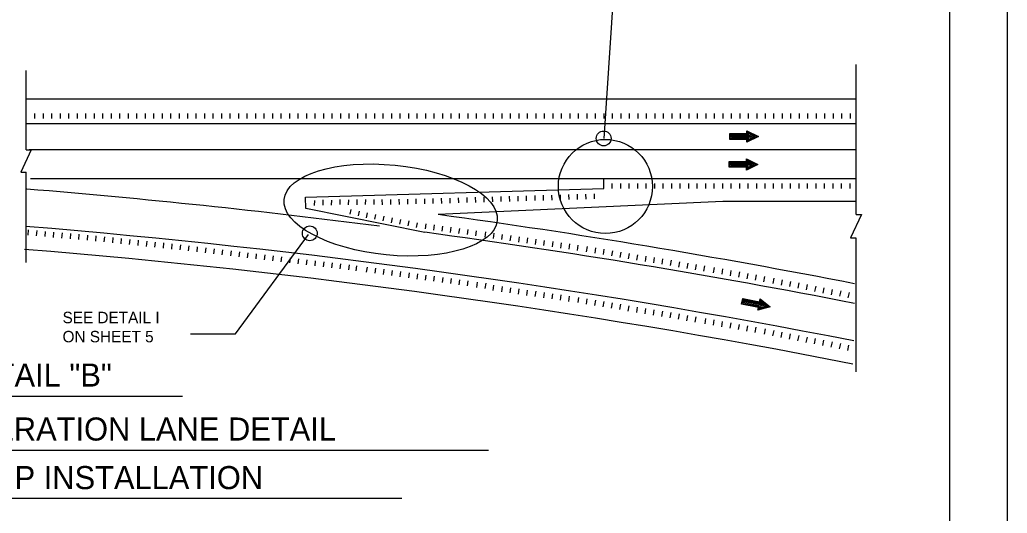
# Model space of a CAD drawing. Extents: x 632008 to 634206, y 294231 to 297795.
# Drawn here: x 632590.2 to 632848.9, y 295746 to 295875.2 of the extents above; entities that cross this region are included whole.
import ezdxf

# ---------------------------------------------------------------- set-up
doc = ezdxf.new("R2010")
doc.units = 0
for name, color, linetype in [('1', 7, 'Continuous'), ('2', 7, 'Continuous'), ('PLT-BNDY', 7, 'Continuous')]:
    doc.layers.add(name, color=color, linetype=linetype)

msp = doc.modelspace()

# ---------------------------------------------------------------- linework, layer by layer
at = {"layer": '1'}
for p, q in [((632747.02, 295902.24), (632743.17, 295844.09)), ((632594.1, 295850.65), (632594.1, 295849.32)), ((632596.33, 295850.65), (632596.33, 295849.32)), ((632598.56, 295850.65), (632598.56, 295849.32)), ((632600.78, 295850.65), (632600.78, 295849.32)), ((632603.01, 295850.65), (632603.01, 295849.32)), ((632605.23, 295850.65), (632605.23, 295849.32)), ((632607.45, 295850.65), (632607.45, 295849.32)), ((632609.68, 295850.65), (632609.68, 295849.32)), ((632611.91, 295850.65), (632611.91, 295849.32)), ((632614.13, 295850.65), (632614.13, 295849.32)), ((632616.35, 295850.65), (632616.35, 295849.32)), ((632618.58, 295850.65), (632618.58, 295849.32)), ((632620.81, 295850.65), (632620.81, 295849.32)), ((632623.03, 295850.65), (632623.03, 295849.32)), ((632625.25, 295850.65), (632625.25, 295849.32)), ((632627.48, 295850.65), (632627.48, 295849.32)), ((632629.7, 295850.65), (632629.7, 295849.32)), ((632631.93, 295850.65), (632631.93, 295849.32)), ((632634.16, 295850.65), (632634.16, 295849.32)), ((632636.38, 295850.65), (632636.38, 295849.32)), ((632638.6, 295850.65), (632638.6, 295849.32)), ((632640.83, 295850.65), (632640.83, 295849.32)), ((632643.05, 295850.65), (632643.05, 295849.32)), ((632645.28, 295850.65), (632645.28, 295849.32)), ((632647.5, 295850.65), (632647.5, 295849.32)), ((632649.73, 295850.65), (632649.73, 295849.32)), ((632651.95, 295850.65), (632651.95, 295849.32)), ((632654.18, 295850.65), (632654.18, 295849.32)), ((632656.4, 295850.65), (632656.4, 295849.32)), ((632658.63, 295850.65), (632658.63, 295849.32)), ((632660.85, 295850.65), (632660.85, 295849.32)), ((632663.08, 295850.65), (632663.08, 295849.32)), ((632665.3, 295850.65), (632665.3, 295849.32)), ((632667.53, 295850.65), (632667.53, 295849.32)), ((632669.75, 295850.65), (632669.75, 295849.32)), ((632671.98, 295850.65), (632671.98, 295849.32)), ((632674.2, 295850.65), (632674.2, 295849.32)), ((632676.43, 295850.65), (632676.43, 295849.32)), ((632678.65, 295850.65), (632678.65, 295849.32)), ((632680.88, 295850.65), (632680.88, 295849.32)), ((632683.1, 295850.65), (632683.1, 295849.32)), ((632685.33, 295850.65), (632685.33, 295849.32)), ((632687.55, 295850.65), (632687.55, 295849.32)), ((632689.78, 295850.65), (632689.78, 295849.32)), ((632692, 295850.65), (632692, 295849.32)), ((632694.23, 295850.65), (632694.23, 295849.32)), ((632696.45, 295850.65), (632696.45, 295849.32)), ((632698.68, 295850.65), (632698.68, 295849.32)), ((632700.9, 295850.65), (632700.9, 295849.32)), ((632703.13, 295850.65), (632703.13, 295849.32)), ((632705.35, 295850.65), (632705.35, 295849.32)), ((632707.58, 295850.65), (632707.58, 295849.32)), ((632709.8, 295850.65), (632709.8, 295849.32)), ((632712.03, 295850.65), (632712.03, 295849.32)), ((632714.25, 295850.65), (632714.25, 295849.32)), ((632716.48, 295850.65), (632716.48, 295849.32)), ((632718.7, 295850.65), (632718.7, 295849.32)), ((632720.93, 295850.65), (632720.93, 295849.32)), ((632723.15, 295850.65), (632723.15, 295849.32)), ((632725.38, 295850.65), (632725.38, 295849.32)), ((632727.6, 295850.65), (632727.6, 295849.32)), ((632729.83, 295850.65), (632729.83, 295849.32)), ((632732.05, 295850.65), (632732.05, 295849.32)), ((632734.28, 295850.65), (632734.28, 295849.32)), ((632736.5, 295850.65), (632736.5, 295849.32)), ((632738.73, 295850.65), (632738.73, 295849.32)), ((632740.95, 295850.65), (632740.95, 295849.32)), ((632743.18, 295850.65), (632743.18, 295849.32)), ((632745.4, 295850.65), (632745.4, 295849.32)), ((632747.63, 295850.65), (632747.63, 295849.32)), ((632749.85, 295850.65), (632749.85, 295849.32)), ((632752.08, 295850.65), (632752.08, 295849.32)), ((632754.3, 295850.65), (632754.3, 295849.32)), ((632756.53, 295850.65), (632756.53, 295849.32)), ((632758.75, 295850.65), (632758.75, 295849.32)), ((632760.98, 295850.65), (632760.98, 295849.32)), ((632763.2, 295850.65), (632763.2, 295849.32)), ((632765.43, 295850.65), (632765.43, 295849.32)), ((632767.65, 295850.65), (632767.65, 295849.32)), ((632769.88, 295850.65), (632769.88, 295849.32)), ((632772.1, 295850.65), (632772.1, 295849.32)), ((632774.33, 295850.65), (632774.33, 295849.32)), ((632776.55, 295850.65), (632776.55, 295849.32)), ((632778.78, 295850.65), (632778.78, 295849.32)), ((632781, 295850.65), (632781, 295849.32)), ((632783.23, 295850.65), (632783.23, 295849.32)), ((632785.45, 295850.65), (632785.45, 295849.32)), ((632787.68, 295850.65), (632787.68, 295849.32)), ((632789.9, 295850.65), (632789.9, 295849.32)), ((632792.13, 295850.65), (632792.13, 295849.32)), ((632794.35, 295850.65), (632794.35, 295849.32)), ((632796.58, 295850.65), (632796.58, 295849.32)), ((632798.8, 295850.65), (632798.8, 295849.32)), ((632801.02, 295850.65), (632801.02, 295849.32)), ((632803.25, 295850.65), (632803.25, 295849.32)), ((632805.48, 295850.65), (632805.48, 295849.32)), ((632807.7, 295850.65), (632807.7, 295849.32)), ((632743.18, 295830.97), (632743.18, 295833.61)), ((632745.4, 295830.97), (632745.4, 295832.3)), ((632747.63, 295830.97), (632747.63, 295832.3)), ((632749.85, 295830.97), (632749.85, 295832.3)), ((632752.08, 295830.97), (632752.08, 295832.3)), ((632754.3, 295830.97), (632754.3, 295832.3)), ((632756.53, 295830.97), (632756.53, 295832.3)), ((632758.75, 295830.97), (632758.75, 295832.3)), ((632760.98, 295830.97), (632760.98, 295832.3)), ((632763.2, 295830.97), (632763.2, 295832.3)), ((632765.43, 295830.97), (632765.43, 295832.3)), ((632767.65, 295830.97), (632767.65, 295832.3)), ((632769.88, 295830.97), (632769.88, 295832.3)), ((632772.1, 295830.97), (632772.1, 295832.3)), ((632774.33, 295830.97), (632774.33, 295832.3)), ((632776.55, 295830.97), (632776.55, 295832.3)), ((632778.78, 295830.97), (632778.78, 295832.3)), ((632781, 295830.97), (632781, 295832.3)), ((632783.23, 295830.97), (632783.23, 295832.3)), ((632785.45, 295830.97), (632785.45, 295832.3)), ((632787.68, 295830.97), (632787.68, 295832.3)), ((632789.9, 295830.97), (632789.9, 295832.3)), ((632792.13, 295830.97), (632792.13, 295832.3)), ((632794.35, 295830.97), (632794.35, 295832.3)), ((632796.58, 295830.97), (632796.58, 295832.3)), ((632798.8, 295830.97), (632798.8, 295832.3)), ((632801.02, 295830.97), (632801.02, 295832.3)), ((632803.25, 295830.97), (632803.25, 295832.3)), ((632805.48, 295830.97), (632805.48, 295832.3)), ((632807.7, 295830.97), (632807.7, 295832.3)), ((632665.17, 295825.75), (632665.08, 295828.71)), ((632667.39, 295827.83), (632667.36, 295826.5)), ((632669.61, 295827.99), (632669.59, 295826.66)), ((632671.84, 295827.94), (632671.81, 295826.61)), ((632674.06, 295828.1), (632674.04, 295826.77)), ((632676.29, 295828.05), (632676.26, 295826.72)), ((632678.51, 295828.07), (632678.49, 295826.74)), ((632680.74, 295828.1), (632680.71, 295826.76)), ((632682.96, 295828.12), (632682.93, 295826.78)), ((632685.19, 295826.73), (632685.16, 295828.07)), ((632687.41, 295826.78), (632687.38, 295828.12)), ((632689.64, 295826.83), (632689.61, 295828.16)), ((632691.86, 295826.88), (632691.83, 295828.21)), ((632694.08, 295826.93), (632694.06, 295828.26)), ((632696.31, 295826.97), (632696.28, 295828.31)), ((632698.52, 295827.04), (632698.48, 295828.37)), ((632700.74, 295827.1), (632700.71, 295828.44)), ((632702.97, 295827.17), (632702.93, 295828.5)), ((632705.19, 295827.23), (632705.15, 295828.57)), ((632707.42, 295827.3), (632707.38, 295828.63)), ((632709.64, 295827.36), (632709.6, 295828.69)), ((632711.87, 295827.42), (632711.83, 295828.76)), ((632714.09, 295827.49), (632714.05, 295828.82)), ((632716.31, 295827.55), (632716.27, 295828.89)), ((632718.54, 295827.62), (632718.5, 295828.95)), ((632720.76, 295827.68), (632720.72, 295829.02)), ((632722.98, 295827.75), (632722.95, 295829.08)), ((632725.21, 295827.81), (632725.17, 295829.14)), ((632727.43, 295827.87), (632727.39, 295829.21)), ((632729.66, 295827.94), (632729.62, 295829.27)), ((632731.88, 295828), (632731.84, 295829.34)), ((632734.1, 295828.07), (632734.07, 295829.4)), ((632736.33, 295828.13), (632736.29, 295829.47)), ((632738.55, 295828.2), (632738.51, 295829.53)), ((632740.78, 295828.26), (632740.74, 295829.59)), ((632696.33, 295819.51), (632665.17, 295825.75)), ((632676.72, 295824.23), (632676.98, 295825.53)), ((632678.9, 295823.79), (632679.16, 295825.09)), ((632681.08, 295823.35), (632681.34, 295824.66)), ((632683.26, 295822.92), (632683.52, 295824.22)), ((632685.44, 295822.48), (632685.7, 295823.78)), ((632687.62, 295822.04), (632687.88, 295823.35)), ((632689.8, 295821.61), (632690.06, 295822.91)), ((632691.98, 295821.17), (632692.24, 295822.48)), ((632592.41, 295818.77), (632592.53, 295820.16)), ((632594.63, 295818.58), (632594.75, 295819.97)), ((632596.84, 295818.39), (632596.96, 295819.77)), ((632599.06, 295818.19), (632599.18, 295819.58)), ((632694.16, 295820.74), (632694.42, 295822.04)), ((632696.45, 295820.42), (632696.63, 295821.74)), ((632698.66, 295820.12), (632698.84, 295821.44)), ((632700.86, 295819.81), (632701.04, 295821.14)), ((632703.06, 295819.51), (632703.24, 295820.84)), ((632705.26, 295819.21), (632705.45, 295820.53)), ((632707.47, 295818.91), (632707.65, 295820.23)), ((632709.67, 295818.6), (632709.85, 295819.93)), ((632712.1, 295818.23), (632712.3, 295819.6)), ((632601.27, 295818), (632601.39, 295819.39)), ((632603.49, 295817.81), (632603.61, 295819.19)), ((632605.7, 295817.61), (632605.82, 295819)), ((632607.92, 295817.42), (632608.04, 295818.81)), ((632610.13, 295817.23), (632610.25, 295818.61)), ((632612.35, 295817), (632612.49, 295818.36)), ((632614.56, 295816.77), (632614.7, 295818.13)), ((632616.77, 295816.54), (632616.91, 295817.89)), ((632618.98, 295816.3), (632619.12, 295817.66)), ((632621.19, 295816.07), (632621.33, 295817.43)), ((632623.4, 295815.84), (632623.55, 295817.19)), ((632625.61, 295815.6), (632625.76, 295816.96)), ((632646.76, 295792.9), (632665.86, 295818.94)), ((632714.3, 295817.91), (632714.5, 295819.29)), ((632716.5, 295817.6), (632716.7, 295818.97)), ((632718.7, 295817.28), (632718.9, 295818.66)), ((632720.9, 295816.97), (632721.1, 295818.34)), ((632723.1, 295816.65), (632723.3, 295818.03)), ((632725.31, 295816.34), (632725.5, 295817.71)), ((632727.51, 295816.02), (632727.7, 295817.4)), ((632729.71, 295815.71), (632729.9, 295817.09)), ((632627.83, 295815.37), (632627.97, 295816.72)), ((632630.04, 295815.14), (632630.18, 295816.49)), ((632632.25, 295814.9), (632632.39, 295816.26)), ((632634.44, 295814.66), (632634.6, 295815.99)), ((632636.65, 295814.4), (632636.81, 295815.73)), ((632638.85, 295814.14), (632639.01, 295815.47)), ((632641.06, 295813.87), (632641.22, 295815.21)), ((632643.27, 295813.61), (632643.43, 295814.94)), ((632645.48, 295813.35), (632645.64, 295814.68)), ((632647.69, 295813.08), (632647.84, 295814.42)), ((632731.91, 295815.4), (632732.11, 295816.77)), ((632734.11, 295815.08), (632734.31, 295816.46)), ((632736.31, 295814.77), (632736.51, 295816.14)), ((632738.7, 295814.37), (632738.94, 295815.79)), ((632740.9, 295814.04), (632741.13, 295815.43)), ((632743.1, 295813.68), (632743.32, 295815.07)), ((632745.29, 295813.32), (632745.52, 295814.71)), ((632747.48, 295812.96), (632747.71, 295814.35)), ((632649.89, 295812.82), (632650.05, 295814.15)), ((632652.1, 295812.56), (632652.26, 295813.89)), ((632654.31, 295812.29), (632654.47, 295813.63)), ((632656.52, 295812.03), (632656.68, 295813.37)), ((632658.72, 295811.77), (632658.88, 295813.1)), ((632660.93, 295811.51), (632661.09, 295812.84)), ((632663.14, 295811.24), (632663.3, 295812.58)), ((632665.35, 295810.98), (632665.51, 295812.31)), ((632667.56, 295810.72), (632667.71, 295812.05)), ((632669.76, 295810.45), (632669.92, 295811.79)), ((632749.68, 295812.6), (632749.91, 295813.99)), ((632751.87, 295812.24), (632752.1, 295813.63)), ((632754.07, 295811.87), (632754.29, 295813.27)), ((632756.26, 295811.51), (632756.49, 295812.9)), ((632758.45, 295811.15), (632758.68, 295812.54)), ((632760.65, 295810.79), (632760.88, 295812.18)), ((632762.84, 295810.43), (632763.07, 295811.82)), ((632671.97, 295810.19), (632672.13, 295811.52)), ((632674.18, 295809.93), (632674.34, 295811.26)), ((632676.39, 295809.67), (632676.55, 295811)), ((632678.35, 295809.43), (632678.51, 295810.76)), ((632681.07, 295809.11), (632681.26, 295810.43)), ((632683.28, 295808.8), (632683.46, 295810.13)), ((632685.48, 295808.5), (632685.66, 295809.83)), ((632687.68, 295808.2), (632687.86, 295809.52)), ((632689.88, 295807.9), (632690.07, 295809.22)), ((632765.03, 295810.07), (632765.26, 295811.46)), ((632767.23, 295809.71), (632767.46, 295811.1)), ((632769.42, 295809.34), (632769.65, 295810.74)), ((632771.96, 295808.92), (632772.21, 295810.31)), ((632774.15, 295808.53), (632774.4, 295809.92)), ((632776.34, 295808.14), (632776.59, 295809.53)), ((632692.09, 295807.59), (632692.27, 295808.92)), ((632694.29, 295807.29), (632694.47, 295808.62)), ((632696.49, 295806.99), (632696.68, 295808.31)), ((632698.7, 295806.69), (632698.88, 295808.01)), ((632700.9, 295806.38), (632701.08, 295807.71)), ((632703.1, 295806.08), (632703.28, 295807.41)), ((632705.3, 295805.78), (632705.49, 295807.1)), ((632707.51, 295805.48), (632707.69, 295806.8)), ((632778.53, 295807.74), (632778.78, 295809.14)), ((632780.72, 295807.35), (632780.97, 295808.75)), ((632782.91, 295806.96), (632783.16, 295808.36)), ((632785.1, 295806.57), (632785.34, 295807.97)), ((632787.58, 295806.13), (632787.85, 295807.52)), ((632789.76, 295805.71), (632790.03, 295807.1)), ((632791.95, 295805.29), (632792.22, 295806.68)), ((632709.94, 295805.1), (632710.13, 295806.47)), ((632712.14, 295804.78), (632712.34, 295806.16)), ((632714.23, 295804.27), (632714.43, 295805.65)), ((632716.44, 295803.96), (632716.63, 295805.34)), ((632718.64, 295803.64), (632718.83, 295805.02)), ((632720.84, 295803.33), (632721.03, 295804.71)), ((632723.04, 295803.01), (632723.24, 295804.39)), ((632725.24, 295802.7), (632725.44, 295804.08)), ((632794.13, 295804.86), (632794.4, 295806.26)), ((632796.31, 295804.44), (632796.58, 295805.84)), ((632798.5, 295804.02), (632798.77, 295805.41)), ((632800.68, 295803.6), (632800.95, 295804.99)), ((632802.86, 295803.18), (632803.13, 295804.57)), ((632805.05, 295802.76), (632805.32, 295804.15)), ((632727.44, 295802.39), (632727.64, 295803.76)), ((632729.64, 295802.07), (632729.84, 295803.45)), ((632731.84, 295801.76), (632732.04, 295803.13)), ((632734.04, 295801.44), (632734.24, 295802.82)), ((632736.47, 295801.1), (632736.67, 295802.47)), ((632738.64, 295800.72), (632738.86, 295802.11)), ((632740.83, 295800.36), (632741.06, 295801.75)), ((632807.23, 295802.33), (632807.5, 295803.73)), ((632743.02, 295800), (632743.25, 295801.39)), ((632745.22, 295799.63), (632745.45, 295801.03)), ((632747.41, 295799.27), (632747.64, 295800.66)), ((632749.6, 295798.91), (632749.83, 295800.3)), ((632751.8, 295798.55), (632752.03, 295799.94)), ((632753.99, 295798.19), (632754.22, 295799.58)), ((632756.19, 295797.83), (632756.41, 295799.22)), ((632758.38, 295797.47), (632758.61, 295798.86)), ((632760.57, 295797.11), (632760.8, 295798.5)), ((632762.77, 295796.74), (632763, 295798.13)), ((632764.96, 295796.38), (632765.19, 295797.77)), ((632767.15, 295796.02), (632767.38, 295797.41)), ((632769.7, 295795.59), (632769.94, 295796.99)), ((632771.89, 295795.2), (632772.13, 295796.6)), ((632774.07, 295794.81), (632774.32, 295796.2)), ((632776.26, 295794.42), (632776.51, 295795.81)), ((632778.45, 295794.03), (632778.7, 295795.42)), ((632780.64, 295793.64), (632780.89, 295795.03)), ((632782.83, 295793.25), (632783.08, 295794.64)), ((632785.31, 295792.81), (632785.58, 295794.2)), ((632787.5, 295792.38), (632787.77, 295793.78)), ((632789.68, 295791.96), (632789.95, 295793.36)), ((632791.86, 295791.54), (632792.13, 295792.93)), ((632794.05, 295791.12), (632794.32, 295792.51)), ((632796.23, 295790.7), (632796.5, 295792.09)), ((632798.41, 295790.28), (632798.68, 295791.67)), ((632800.6, 295789.85), (632800.86, 295791.25)), ((632802.78, 295789.43), (632803.05, 295790.83)), ((632804.96, 295789.01), (632805.23, 295790.4)), ((632807.14, 295788.59), (632807.41, 295789.98)), ((632569.68, 295776.65), (632632.82, 295776.65))]:
    msp.add_line(p, q, dxfattribs=at)
msp.add_lwpolyline([(632833.86, 295433.62), (632833.86, 295997.62), (632047.86, 295997.62), (632047.86, 295433.62), (632833.86, 295433.62), (632833.86, 295459.98), (632633.86, 295459.98), (632633.86, 295524.66), (632833.86, 295524.66), (632833.86, 295553.62), (632633.86, 295553.62), (632633.86, 295433.62), (632712.66, 295433.62), (632712.66, 295459.98), (632712.66, 295433.62), (632789.66, 295433.62), (632789.66, 295459.98), (632789.66, 295447.66), (632833.86, 295447.66)], dxfattribs=at)
msp.add_lwpolyline([(632833.86, 295433.62), (632833.86, 295997.62), (632047.86, 295997.62), (632047.86, 295433.62), (632833.86, 295433.62), (632833.86, 295459.98), (632633.86, 295459.98), (632633.86, 295524.66), (632833.86, 295524.66), (632833.86, 295553.62), (632633.86, 295553.62), (632633.86, 295433.62), (632712.66, 295433.62), (632712.66, 295459.98), (632712.66, 295433.62), (632789.66, 295433.62), (632789.66, 295459.98), (632789.66, 295447.66), (632833.86, 295447.66)], dxfattribs=at)
msp.add_lwpolyline([(632833.86, 295433.62), (632833.86, 295997.62), (632047.86, 295997.62), (632047.86, 295433.62), (632833.86, 295433.62), (632833.86, 295459.98), (632633.86, 295459.98), (632633.86, 295524.66), (632833.86, 295524.66), (632833.86, 295553.62), (632633.86, 295553.62), (632633.86, 295433.62), (632712.66, 295433.62), (632712.66, 295459.98), (632712.66, 295433.62), (632789.66, 295433.62), (632789.66, 295459.98), (632789.66, 295447.66), (632833.86, 295447.66)], dxfattribs=at)
msp.add_lwpolyline([(632833.86, 295433.62), (632833.86, 295997.62), (632047.86, 295997.62), (632047.86, 295433.62), (632833.86, 295433.62), (632833.86, 295459.98), (632633.86, 295459.98), (632633.86, 295524.66), (632833.86, 295524.66), (632833.86, 295553.62), (632633.86, 295553.62), (632633.86, 295433.62), (632712.66, 295433.62), (632712.66, 295459.98), (632712.66, 295433.62), (632789.66, 295433.62), (632789.66, 295459.98), (632789.66, 295447.66), (632833.86, 295447.66)], dxfattribs=at)
for centre, radius in [((632743.17, 295844.09), 1.94), ((632743.61, 295831.53), 12.32), ((632666.19, 295819.25), 1.94)]:
    msp.add_circle(centre, radius, dxfattribs=at)
msp.add_ellipse((632687.36, 295825.35), major_axis=(-27.9, 2.75), ratio=0.420922, dxfattribs=at)
at = {"layer": '2'}
for p, q in [((632591.93, 295841.14), (632591.93, 295861.91)), ((632809.32, 295824.2), (632809.32, 295863.47)), ((632809.32, 295854.35), (632591.93, 295854.35)), ((632591.93, 295848.01), (632809.32, 295848.01)), ((632593.2, 295841.14), (632590.51, 295835.3)), ((632591.93, 295841.14), (632593.2, 295841.14)), ((632592.69, 295841.23), (632809.32, 295841.23)), ((632590.51, 295835.3), (632591.93, 295835.3)), ((632591.93, 295811.6), (632591.93, 295835.3)), ((632593.05, 295833.61), (632743.18, 295833.61)), ((632743.18, 295833.61), (632809.32, 295833.61)), ((632665.08, 295828.71), (632743.18, 295830.97)), ((632774.35, 295827.61), (632699.82, 295824.16)), ((632809.32, 295827.61), (632774.35, 295827.61)), ((632810.65, 295824.2), (632807.83, 295818.1)), ((632809.32, 295824.2), (632810.65, 295824.2)), ((632807.83, 295818.1), (632809.16, 295818.1)), ((632809.32, 295782.96), (632809.32, 295818.1)), ((632634.95, 295792.9), (632646.76, 295792.9)), ((632489.49, 295762.45), (632713.03, 295762.45)), ((632512.7, 295749.93), (632690.31, 295749.93))]:
    msp.add_line(p, q, dxfattribs=at)
for points in [[(632776.18, 295845.35), (632780.69, 295845.35), (632780.69, 295846.1), (632783.68, 295844.6), (632780.69, 295843.1), (632780.69, 295843.85), (632776.18, 295843.85), (632776.18, 295845.35)], [(632776.33, 295845.2), (632780.84, 295845.2), (632780.84, 295845.8), (632783.23, 295844.6), (632780.84, 295843.4), (632780.84, 295844), (632776.33, 295844), (632776.33, 295845.05), (632781.14, 295845.05), (632780.98, 295845.5), (632782.64, 295844.6), (632780.98, 295843.7), (632781.14, 295844.3), (632776.64, 295844.3), (632776.64, 295844.9), (632781.43, 295844.9), (632782.04, 295844.6), (632781.43, 295844.3), (632781.43, 295844.6), (632776.78, 295844.6)], [(632776.33, 295845.2), (632776.18, 295845.35)], [(632776.06, 295838.04), (632780.56, 295838.04), (632780.56, 295838.79), (632783.57, 295837.29), (632780.56, 295835.79), (632780.56, 295836.54), (632776.06, 295836.54), (632776.06, 295838.04)], [(632776.21, 295837.89), (632776.06, 295838.04)], [(632776.21, 295837.89), (632780.72, 295837.89), (632780.72, 295838.49), (632783.12, 295837.29), (632780.72, 295836.09), (632780.72, 295836.69), (632776.21, 295836.69), (632776.21, 295837.74), (632781.01, 295837.74), (632780.87, 295838.19), (632782.52, 295837.29), (632780.87, 295836.39), (632781.01, 295836.99), (632776.51, 295836.99), (632776.51, 295837.59), (632781.32, 295837.59), (632781.91, 295837.29), (632781.32, 295836.99), (632781.32, 295837.29), (632776.66, 295837.29)], [(632779.57, 295802.16), (632783.99, 295801.33), (632784.13, 295802.06), (632786.8, 295800.03), (632783.57, 295799.11), (632783.71, 295799.85), (632779.29, 295800.69), (632779.57, 295802.16)], [(632779.69, 295801.98), (632784.11, 295801.15), (632784.22, 295801.74), (632786.36, 295800.11), (632783.78, 295799.38), (632783.89, 295799.97), (632779.47, 295800.8), (632779.66, 295801.84), (632784.38, 295800.94), (632784.31, 295801.42), (632785.77, 295800.22), (632783.98, 295799.65), (632784.24, 295800.21), (632779.82, 295801.04), (632779.93, 295801.63), (632784.64, 295800.75), (632785.18, 295800.34), (632784.53, 295800.16), (632784.59, 295800.45), (632780.02, 295801.31)], [(632779.69, 295801.98), (632779.57, 295802.16)]]:
    msp.add_lwpolyline(points, dxfattribs=at)
for centre, radius, start, end in [((632433.58, 293882.14), 1955.11, 82.62863, 85.34936), ((632433.99, 293887.21), 1955.11, 78.94473, 82.18528), ((632433.15, 293872.38), 1955.11, 78.92606, 85.34664), ((632433.58, 293882.14), 1955.11, 78.93496, 82.27653), ((632433.15, 293872.38), 1949.11, 78.90022, 85.34001)]:
    msp.add_arc(centre, radius, start, end, dxfattribs=at)
at = {"layer": 'PLT-BNDY'}
msp.add_lwpolyline([(632007.86, 296012.62), (632848.86, 296012.62), (632848.86, 295418.62), (632007.86, 295418.62)], close=True, dxfattribs=at)

# ---------------------------------------------------------------- texts
at = {"layer": '1'}
for s, height, p in [('SEE DETAIL I', 3, (632601.43, 295795.71)), ('ON SHEET 5', 3, (632601.43, 295790.71)), ('DETAIL "B"', 6.039, (632572.7, 295779.12)), ('ACCELERATION/DECELERATION LANE DETAIL', 6.0395, (632491.28, 295764.99)), ('FOR RUMBLE STRIP INSTALLATION', 6.0395, (632515.28, 295752.27))]:
    msp.add_text(s, height=height, dxfattribs=at).set_placement(p)

doc.saveas('drawing.dxf')
